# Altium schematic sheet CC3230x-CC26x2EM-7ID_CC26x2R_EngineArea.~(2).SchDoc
size 558 x 431 mm; Date: Not shown in title block; ApprovedBy: Not shown in title block; CheckedBy: Not shown in title block; Author: Not shown in title block; CompanyName: Not shown in title block; Engineer: Not shown in title block; Organization: Not shown in title block; Address1: Not shown in title block; Address2: Not shown in title block; Address3: Not shown in title block; Address4: Not shown in title block; DocumentNumber: 3; Revision: Use project parameter SCH_Rev; SheetNumber: 3; SheetTotal: 5; PageSetup: Record=PageOptions¦CenterHorizontal=True¦CenterVertical=True¦PrintScale=1.00¦XCorrection=1.00¦YCorrection=1.00¦PrintKind=0¦BorderSize=5000000¦LeftOffset=0¦BottomOffset=0¦Orientation=2¦PaperLength=1000¦PaperWidth=1000¦Scale=100¦PaperSource=15¦PrintQuality=600¦MediaType=1¦DitherType=10¦PaperKind=Letter¦PrintScaleMode=1
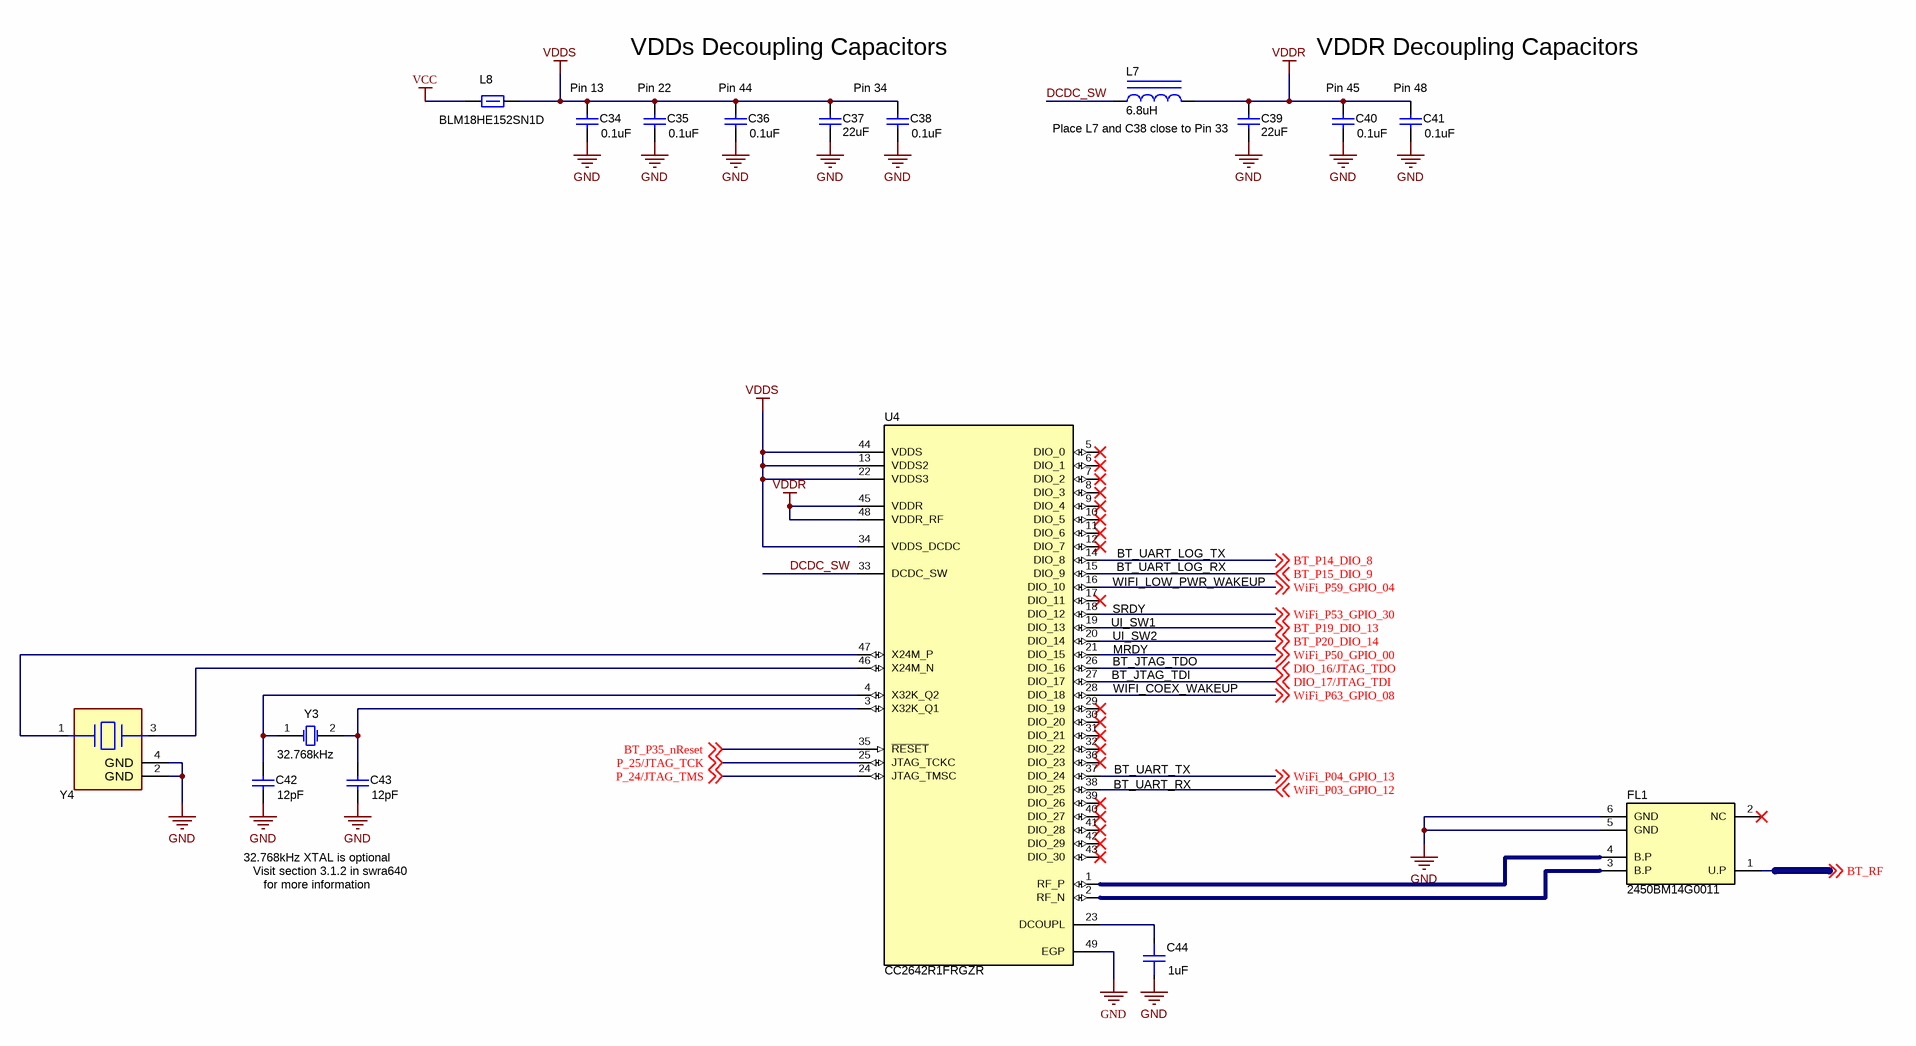
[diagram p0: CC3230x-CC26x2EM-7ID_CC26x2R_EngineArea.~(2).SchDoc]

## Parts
C34  ValueDisplayed: 0.1uF  [0201]  (hidden comment: GRM033Z71C104KE14D)
C35  ValueDisplayed: 0.1uF  [0201]  (hidden comment: GRM033Z71C104KE14D)
C36  ValueDisplayed: 0.1uF  [0201]  (hidden comment: GRM033Z71C104KE14D)
C37  ValueDisplayed: 22uF  [0402]  (hidden comment: GRM155R60J226ME11D)
C38  ValueDisplayed: 0.1uF  [0201]  (hidden comment: GRM033Z71C104KE14D)
C39  ValueDisplayed: 22uF  [0402]  (hidden comment: GRM155R60J226ME11D)
C40  ValueDisplayed: 0.1uF  [0201]  (hidden comment: GRM033Z71C104KE14D)
C41  ValueDisplayed: 0.1uF  [0201]  (hidden comment: GRM033Z71C104KE14D)
C42  ValueDisplayed: 12pF  [0201_033]  (hidden comment: C0603C0G1E120J030BA)
C43  ValueDisplayed: 12pF  [0201_033]  (hidden comment: C0603C0G1E120J030BA)
C44  ValueDisplayed: 1uF  [FP-JMK063BC6105MP-F_0201-MFG]  (hidden comment: JMK063BC6105MP-F)
FL1  2450BM14G0011  [Johanson_2450BM14G0011]
L7  ValueDisplayed: 6.8uH  [0805_HV]  (hidden comment: MLZ2012N6R8LT000)
L8  BLM18HE152SN1D  [0603]
U4  CC2642R1FRGZR  [RGZ0048A]
Y3  Frequency_Fixed: 32.768kHz  [Epson_FC-135]  (hidden comment: FC-135 32.7680KA-AG0)
Y4  CX2016DB48000C0WPLA2  [FP-CX2016DB48000C0WPLA2_SMD4-MFG]  (value not drawn)

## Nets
GND: C34.2 C35.2 C36.2 C37.2 C38.2 C39.2 C40.2 C41.2 C42.2 C43.2 C44.1 FL1.5(GND) FL1.6(GND) U4.49(EGP) Y4.2(GND) Y4.4(GND)
VCC: L8.1
VDDR: C39.1 C40.1 C41.1 L7.2 U4.45(VDDR) U4.48(VDDR_RF)
VDDS: C34.1 C35.1 C36.1 C37.1 C38.1 L8.2 U4.13(VDDS2) U4.22(VDDS3) U4.34(VDDS_DCDC) U4.44(VDDS)
BT_P14_DIO_8: U4.14(DIO_8) ; off-sheet BT_P14_DIO_8
BT_P15_DIO_9: U4.15(DIO_9) ; off-sheet BT_P15_DIO_9
BT_P19_DIO_13: U4.19(DIO_13) ; off-sheet BT_P19_DIO_13
BT_P20_DIO_14: U4.20(DIO_14) ; off-sheet BT_P20_DIO_14
BT_P35_nReset: U4.35(~{RESET}) ; off-sheet BT_P35_nReset
BT_RF: FL1.1(U.P) ; off-sheet BT_RF
DCDC_SW: L7.1 U4.33(DCDC_SW)
DIO_16/JTAG_TDO: U4.26(DIO_16) ; off-sheet DIO_16/JTAG_TDO
DIO_17/JTAG_TDI: U4.27(DIO_17) ; off-sheet DIO_17/JTAG_TDI
P_24/JTAG_TMS: U4.24(JTAG_TMSC) ; off-sheet P_24/JTAG_TMS
P_25/JTAG_TCK: U4.25(JTAG_TCKC) ; off-sheet P_25/JTAG_TCK
WiFi_P03_GPIO_12: U4.38(DIO_25) ; off-sheet WiFi_P03_GPIO_12
WiFi_P04_GPIO_13: U4.37(DIO_24) ; off-sheet WiFi_P04_GPIO_13
WiFi_P50_GPIO_00: U4.21(DIO_15) ; off-sheet WiFi_P50_GPIO_00
WiFi_P53_GPIO_30: U4.18(DIO_12) ; off-sheet WiFi_P53_GPIO_30
WiFi_P59_GPIO_04: U4.16(DIO_10) ; off-sheet WiFi_P59_GPIO_04
WiFi_P63_GPIO_08: U4.28(DIO_18) ; off-sheet WiFi_P63_GPIO_08
NetC42_1: C42.1 U4.4(X32K_Q2) Y3.1(OSC1)
NetC43_1: C43.1 U4.3(X32K_Q1) Y3.2(OSC2)
NetC44_2: C44.2 U4.23(DCOUPL)
NetFL1_3: FL1.3(B.P) U4.2(RF_N)
NetFL1_4: FL1.4(B.P) U4.1(RF_P)
NetU4_46: U4.46(X24M_N) Y4.3(2_HOT)
NetU4_47: U4.47(X24M_P) Y4.1(1_HOT)

Not connected (* = marked no-connect by the designer): FL1 2(NC)*; U4 5(DIO_0)* 6(DIO_1)* 7(DIO_2)* 8(DIO_3)* 9(DIO_4)* 10(DIO_5)* 11(DIO_6)* 12(DIO_7)* 17(DIO_11)* 29(DIO_19)* 30(DIO_20)* 31(DIO_21)* 32(DIO_22)* 36(DIO_23)* 39(DIO_26)* 40(DIO_27)* 41(DIO_28)* 42(DIO_29)* 43(DIO_30)*

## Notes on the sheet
- (near C34) Pin 13
- (near C35) Pin 22
- (near C36) Pin 44
- VDDs Decoupling Capacitors
- Pin 34
- (near C40) Pin 45
- (near C41) Pin 48
- VDDR Decoupling Capacitors
- Place L7 and C38 close to Pin 33
- BT_UART_LOG_TX
- BT_UART_LOG_RX
- (near U4) SRDY
- (near U4) UI_SW1
- (near U4) UI_SW2
- WIFI_LOW_PWR_WAKEUP
- (near U4) MRDY
- (near U4) BT_JTAG_TDI
- (near U4) BT_JTAG_TDO
- WIFI_COEX_WAKEUP
- (near U4) BT_UART_TX
- (near U4) BT_UART_RX
- 32.768kHz XTAL is optional
- for more information
- Visit section 3.1.2 in swra640

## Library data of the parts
C34-C36 C38 C40 C41 = CMP-0064970-1: CAP, CERM, 0.1 uF, 16 V,+/- 10%, X7R, 0201; Manufacturer: MuRata; TaMin_C: -55°C; Polarized: N; SizeAreaWB_mm2: 2.08; Value1: Unknown; U/M: EA; Value: 0.1uF; TaMax_C: 125°C; SizeZ_mm: 0.26; SizeX_mm: 0.6; SizeY_mm: 0.3; Value2: 16V; SizeArea_mm2: 0.18; CompType: Capacitor; Cap_F: 100nF; AEC Category: Q200
C37 C39 = CMP-0006545-2: CAP, CERM, 22 uF, 6.3 V, +/- 20%, X5R, 0402; Manufacturer: MuRata; TaMin_C: -55°C; Polarized: N; SizeAreaWB_mm2: 3; Value1: Unknown; U/M: EA; Value: 22uF; TaMax_C: 85°C; SizeZ_mm: 0.6; SizeY_mm: 0.5; Value2: 6.3V; CompType: Capacitor; SizeX_mm: 1; Cap_F: 22µF; AEC Category: Q200
C42 C43 = CMP-0009633-3: CAP, CERM, 12 pF, 25 V, +/- 5%, C0G/NP0, 0201; Manufacturer: TDK; TaMin_C: -55°C; ESR_ohm: 0; Polarized: N; SizeAreaWB_mm2: 2.08; Value1: 0 ohm; U/M: EA; Value: 12pF; TaMax_C: 125°C; SizeZ_mm: 0.33; SizeX_mm: 0.6; SizeY_mm: 0.3; Cap_Case: 0201; Value2: 25V; SizeArea_mm2: 0.18; CompType: Capacitor; IRMS_A: 0A; AEC Category: Q200
C44 = CMP-0089441-1: 1µF ±20% 6.3V Ceramic Capacitor X6S 0201 (0603 Metric); Manufacturer: Taiyo Yuden; AEC Qualified: No; TempCo: 22%; SizeZ_mm: 0.39mm
FL1 = CMP-0001890-2: 2.4GHz Impedance Matched Balun + embedded FCC/ETSI Band Pass Filter, SMD; Manufacturer: Johanson Technology; SizeZ_mm: 0.7; SizeX_mm: 1.6; SizeY_mm: 0.8; SizeAreaWB_mm2: 4.68; SizeArea_mm2: 1.28
L7 = CMP-0062727-1: Inductor, Multilayer, Ferrite, 6.8 uH, 0.11 A, 0.25 ohm, SMD; Manufacturer: TDK; Isat: 0.11A @ 50% inductance drop; Irms: 0.55A @ 20C rise; Green_Lifecycle: Active; SizeAreaWB_mm2: 6.75; DCR_ohm: 2.5d; Green_REACh: Passed; Value: 6.8uH; Imax_A: 1.1dA; SizeZ_mm: 1.45; SizeX_mm: 2; SizeY_mm: 1.25; Value2: 0.11A; SizeArea_mm2: 2.5; Ind_H: 6.8µH; AEC Category: Q200
L8 = CMP-0003349-2: Ferrite Bead, 1500 ohm @ 100 MHz, 0.5 A, 0603; Manufacturer: MuRata; Ztyp@1GHz_Ohm: 1.5k; SizeAreaWB_mm2: 4.68; DCR_ohm: 5d; Value1: 0.5 ohm; Imax_A: 5dA; SizeZ_mm: 1; SizeX_mm: 1.6; SizeY_mm: 0.8; Value2: 0.5A; SizeArea_mm2: 1.28
U4 = CMP-0083675-2: SimpleLink(TM) Bluetooth(R) 5 low energy Wireless MCU, RGZ0048A (VQFN-48); Alternate Manufacturer: Texas Instruments; Alternate PartNumber: CC2642R1FRGZT; SizeZ_mm: 1; AEC Category: Q200; SizeY_mm: 7; Rating: #N/A; SizeAreaWB_mm2: 81; AEC Qualified: N; CompType: IC; SizeArea_mm2: 49
Y3 = CMP-0079303-1: Crystal, 32.768 KHz, 20 ppm, 7 pF, SMD; Manufacturer: Epson; TaMin_C: -40°C; Frequency Tolerance: 20 ppm; Load Capacitance: 7 pF; TaMax_C: 85°C; AEC Qualified: N; AEC Category: Q200
Y4 = CMP-0088076-1: 48MHz ±20ppm Crystal 7pF 50 Ohms 4-SMD, No Lead; Manufacturer: Kyocera; Symbol Name: SYM-CX2016DB48000C0WPLA2; SizeZ_mm: 0.45mm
